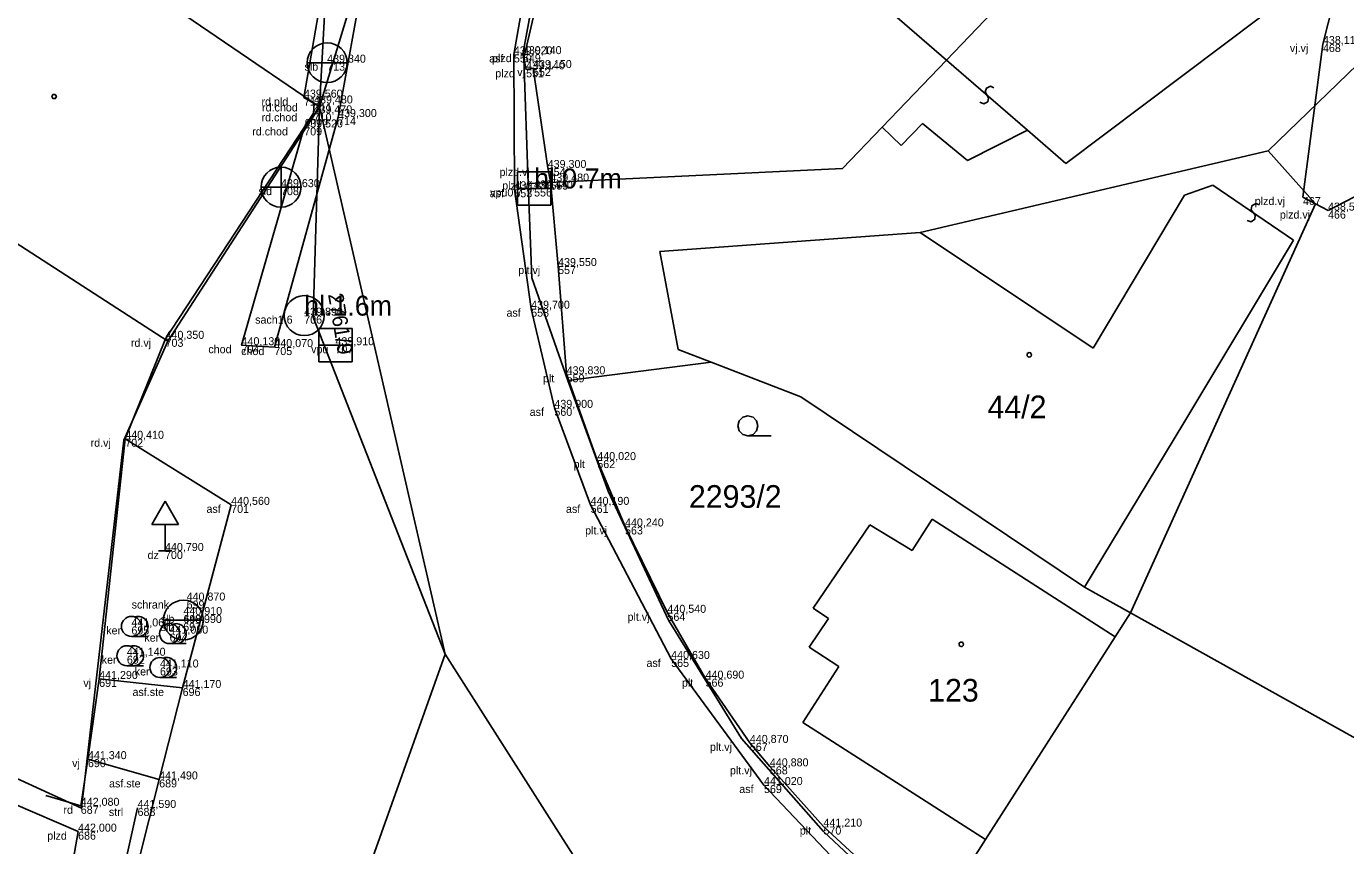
# Model space of a CAD drawing. Extents: x -747792 to -745414, y -1093712 to -1091463.
# Drawn here: x -746697.99 to -746648.52, y -1093111.16 to -1093080.43 of the extents above; entities that cross this region are included whole.
import ezdxf

# ---------------------------------------------------------------- set-up
doc = ezdxf.new("R2010")
doc.units = 0
for name, color, linetype in [('Budovy', 7, 'Continuous'), ('Hladina', 7, 'Continuous'), ('Koleje_dopravní prvky', 7, 'Continuous'), ('Kultury', 7, 'Continuous'), ('Nezařazené objekty', 7, 'Continuous'), ('Nivelační značky_hrany', 7, 'Continuous'), ('Názvy obcí_ulic', 7, 'Continuous'), ('Ploty_opěrné zdi', 7, 'Continuous'), ('Popisy objektů_povrchů', 7, 'Continuous'), ('Pracovní_bod JDTM STC_VC - výška', 7, 'Continuous'), ('Pracovní_bod PPBP - výška', 7, 'Continuous'), ('Pracovní_bod PPBP - číslo', 7, 'Continuous'), ('Pracovní_bod ZPBP - číslo', 7, 'Continuous'), ('Rozhraní ploch', 7, 'Continuous'), ('Stromy_porost', 7, 'Continuous'), ('Výškopis', 7, 'Continuous'), ('Čísla popisná_parcelní', 7, 'Continuous')]:
    doc.layers.add(name, color=color, linetype=linetype)

msp = doc.modelspace()

# ---------------------------------------------------------------- linework, layer by layer
at = {"layer": 'Budovy'}
msp.add_lwpolyline([(-746670.93, -1093095.79), (-746671.12, -1093095.74), (-746671.255, -1093095.6), (-746671.305, -1093095.415), (-746671.255, -1093095.23), (-746671.12, -1093095.09), (-746670.93, -1093095.04), (-746670.74, -1093095.09), (-746670.605, -1093095.23), (-746670.555, -1093095.415), (-746670.605, -1093095.6), (-746670.74, -1093095.74), (-746670.93, -1093095.79), (-746670.055, -1093095.79)], dxfattribs=at)
at = {"layer": 'Hladina'}
for p, q in [((-746649.37, -1093081.09), (-746649.37, -1093081.09)), ((-746686.71, -1093081.79), (-746686.71, -1093081.79)), ((-746679.71, -1093081.48), (-746679.71, -1093081.48)), ((-746679.37, -1093081.47), (-746679.37, -1093081.47)), ((-746679.25, -1093082.04), (-746679.25, -1093082.04)), ((-746678.99, -1093081.99), (-746678.99, -1093081.99)), ((-746687.58, -1093083.1), (-746687.58, -1093083.1)), ((-746687.2, -1093083.32), (-746687.2, -1093083.32)), ((-746687.22, -1093083.69), (-746687.22, -1093083.69)), ((-746686.3, -1093083.83), (-746686.3, -1093083.83)), ((-746687.57, -1093084.22), (-746687.57, -1093084.22)), ((-746678.44, -1093085.74), (-746678.44, -1093085.74)), ((-746678.34, -1093086.25), (-746678.34, -1093086.25)), ((-746688.44, -1093086.46), (-746688.44, -1093086.46)), ((-746679.69, -1093086.54), (-746679.69, -1093086.54)), ((-746678.95, -1093086.51), (-746678.95, -1093086.51)), ((-746650.12, -1093086.83), (-746650.12, -1093086.83)), ((-746649.18, -1093087.34), (-746649.18, -1093087.34)), ((-746678.05, -1093089.42), (-746678.05, -1093089.42)), ((-746687.57, -1093091.28), (-746687.57, -1093091.28)), ((-746679.06, -1093091.02), (-746679.06, -1093091.02)), ((-746692.77, -1093092.15), (-746692.77, -1093092.15)), ((-746689.92, -1093092.39), (-746689.92, -1093092.39)), ((-746688.69, -1093092.46), (-746688.69, -1093092.46)), ((-746686.4, -1093092.39), (-746686.4, -1093092.39)), ((-746677.73, -1093093.48), (-746677.73, -1093093.48)), ((-746678.19, -1093094.74), (-746678.19, -1093094.74)), ((-746694.28, -1093095.9), (-746694.28, -1093095.9)), ((-746676.58, -1093096.7), (-746676.58, -1093096.7)), ((-746690.31, -1093098.38), (-746690.31, -1093098.38)), ((-746676.83, -1093098.38), (-746676.83, -1093098.38)), ((-746675.54, -1093099.19), (-746675.54, -1093099.19)), ((-746692.79, -1093100.11), (-746692.79, -1093100.11)), ((-746691.98, -1093101.97), (-746691.98, -1093101.97)), ((-746692.1, -1093102.51), (-746692.1, -1093102.51)), ((-746673.95, -1093102.43), (-746673.95, -1093102.43)), ((-746694.05, -1093102.94), (-746694.05, -1093102.94)), ((-746692.62, -1093103.21), (-746692.62, -1093103.21)), ((-746692.11, -1093102.81), (-746692.11, -1093102.81)), ((-746694.22, -1093104.04), (-746694.22, -1093104.04)), ((-746673.81, -1093104.16), (-746673.81, -1093104.16)), ((-746692.98, -1093104.48), (-746692.98, -1093104.48)), ((-746695.26, -1093104.91), (-746695.26, -1093104.91)), ((-746672.52, -1093104.9), (-746672.52, -1093104.9)), ((-746692.13, -1093105.25), (-746692.13, -1093105.25)), ((-746670.86, -1093107.31), (-746670.86, -1093107.31)), ((-746695.68, -1093107.92), (-746695.68, -1093107.92)), ((-746670.11, -1093108.19), (-746670.11, -1093108.19)), ((-746693.01, -1093108.68), (-746693.01, -1093108.68)), ((-746670.33, -1093108.89), (-746670.33, -1093108.89)), ((-746695.95, -1093109.67), (-746695.95, -1093109.67)), ((-746693.82, -1093109.75), (-746693.82, -1093109.75)), ((-746696.05, -1093110.64), (-746696.05, -1093110.64)), ((-746668.1, -1093110.45), (-746668.1, -1093110.45))]:
    msp.add_line(p, q, dxfattribs=at)
at = {"layer": 'Kultury'}
for points in [[(-746675.52, -1093071.26), (-746663.49, -1093081.69)], [(-746697.68, -1093076.15), (-746687, -1093083.45)], [(-746660.45, -1093084.32), (-746663.49, -1093081.69)], [(-746662.234, -1093083.272), (-746662.088, -1093083.333), (-746661.941, -1093083.255), (-746661.906, -1093083.107), (-746662.032, -1093082.885), (-746661.986, -1093082.74), (-746661.838, -1093082.676), (-746661.706, -1093082.738)], [(-746704, -1093084.92), (-746692.69, -1093092.24)], [(-746654.56, -1093086.76), (-746653.5, -1093086.39)], [(-746650.47, -1093088.45), (-746653.5, -1093086.39)], [(-746657.98, -1093092.5), (-746654.56, -1093086.76)], [(-746652.216, -1093087.716), (-746652.064, -1093087.759), (-746651.928, -1093087.665), (-746651.91, -1093087.514), (-746652.06, -1093087.308), (-746652.031, -1093087.159), (-746651.892, -1093087.078), (-746651.754, -1093087.124)], [(-746664.47, -1093088.16), (-746657.98, -1093092.5)], [(-746654.59, -1093095.3), (-746650.47, -1093088.45)], [(-746658.31, -1093101.47), (-746654.59, -1093095.3)]]:
    msp.add_lwpolyline(points, dxfattribs=at)
at = {"layer": 'Nezařazené objekty'}
for points in [[(-746678.99, -1093081.99), (-746679.25, -1093082.04), (-746679.37, -1093081.47), (-746678.95, -1093079.16), (-746678.16, -1093076.39), (-746677.05, -1093073.87), (-746675.55, -1093071.24)], [(-746687.58, -1093083.1), (-746686.77, -1093078.39), (-746686.2, -1093076.08), (-746685.66, -1093074.34)], [(-746678.34, -1093086.25), (-746678.44, -1093085.74)], [(-746649.18, -1093087.34), (-746650.12, -1093086.83)], [(-746675.54, -1093099.19), (-746676.58, -1093096.7), (-746677.73, -1093093.48), (-746678.05, -1093089.42)], [(-746670.86, -1093107.31), (-746672.52, -1093104.9), (-746673.95, -1093102.43)], [(-746664.26, -1093113.75), (-746666.3, -1093112.11), (-746668.1, -1093110.45), (-746670.11, -1093108.19)], [(-746696.94, -1093115.72), (-746696.05, -1093110.64), (-746698.49, -1093109.58)]]:
    msp.add_lwpolyline(points, dxfattribs=at)
at = {"layer": 'Nivelační značky_hrany'}
for points in [[(-746660.99, -1093060), (-746658.44, -1093054.36), (-746660.29, -1093053.55), (-746661.8, -1093053.25), (-746663.42, -1093053.5), (-746664.3, -1093053.85), (-746664.96, -1093054.44), (-746666.14, -1093054.24), (-746674.99, -1093068.6), (-746677.6, -1093073.69), (-746678.64, -1093076.35), (-746679.29, -1093079.05), (-746679.71, -1093081.48), (-746679.69, -1093086.54), (-746679.06, -1093091.02), (-746678.19, -1093094.74), (-746676.83, -1093098.38), (-746673.81, -1093104.16), (-746670.33, -1093108.89), (-746666.68, -1093112.75), (-746659.26, -1093118.75), (-746651.34, -1093125.01), (-746630.74, -1093138.49)], [(-746675.68, -1093055.2), (-746675.11, -1093056), (-746675.34, -1093056.75), (-746680.83, -1093065.77), (-746683.01, -1093071), (-746684.01, -1093073.81), (-746684.88, -1093076.49), (-746685.33, -1093078.52), (-746686.3, -1093083.83), (-746688.69, -1093092.46), (-746689.92, -1093092.39), (-746687.57, -1093084.22)], [(-746696.94, -1093115.72), (-746694.86, -1093116.03), (-746693.01, -1093108.68), (-746692.13, -1093105.25), (-746690.31, -1093098.38), (-746694.28, -1093095.9)], [(-746695.26, -1093104.91), (-746692.13, -1093105.25)], [(-746695.68, -1093107.92), (-746693.01, -1093108.68)]]:
    msp.add_lwpolyline(points, dxfattribs=at)
at = {"layer": 'Názvy obcí_ulic'}
for p, q in [((-746692.79, -1093098.244), (-746693.29, -1093099.11)), ((-746692.79, -1093098.244), (-746692.29, -1093099.11)), ((-746693.29, -1093099.11), (-746692.29, -1093099.11)), ((-746692.79, -1093100.11), (-746692.79, -1093099.11)), ((-746693.04, -1093100.11), (-746692.54, -1093100.11))]:
    msp.add_line(p, q, dxfattribs=at)
at = {"layer": 'Ploty_opěrné zdi'}
for points in [[(-746696.905, -1093082.985), (-746696.86, -1093083.06), (-746696.905, -1093083.135), (-746696.995, -1093083.135), (-746697.04, -1093083.06), (-746696.995, -1093082.985)], [(-746660.38, -1093092.665), (-746660.33, -1093092.675), (-746660.305, -1093092.72), (-746660.295, -1093092.75), (-746660.305, -1093092.795), (-746660.345, -1093092.83), (-746660.38, -1093092.835), (-746660.425, -1093092.82), (-746660.455, -1093092.79), (-746660.465, -1093092.75), (-746660.455, -1093092.705), (-746660.415, -1093092.67)], [(-746662.93, -1093103.525), (-746662.88, -1093103.535), (-746662.855, -1093103.58), (-746662.845, -1093103.61), (-746662.855, -1093103.655), (-746662.895, -1093103.69), (-746662.93, -1093103.695), (-746662.975, -1093103.68), (-746663.005, -1093103.65), (-746663.015, -1093103.61), (-746663.005, -1093103.565), (-746662.965, -1093103.53)]]:
    msp.add_lwpolyline(points, close=True, dxfattribs=at)
at = {"layer": 'Popisy objektů_povrchů'}
for points in [[(-746692.77, -1093092.15), (-746687.57, -1093084.22), (-746687.22, -1093083.69), (-746687.2, -1093083.32), (-746687.58, -1093083.1)], [(-746695.26, -1093104.91), (-746694.28, -1093095.9)], [(-746695.68, -1093107.92), (-746695.26, -1093104.91)], [(-746697.26, -1093109.28), (-746695.95, -1093109.67), (-746695.68, -1093107.92)]]:
    msp.add_lwpolyline(points, dxfattribs=at)
at = {"layer": 'Pracovní_bod JDTM STC_VC - výška'}
msp.add_lwpolyline([(-746693.82, -1093109.75), (-746694.88, -1093114.52)], dxfattribs=at)
at = {"layer": 'Pracovní_bod PPBP - výška'}
for points in [[(-746650.12, -1093086.83), (-746649.37, -1093081.09), (-746648.4, -1093077.24)], [(-746678.44, -1093085.74), (-746678.99, -1093081.99)], [(-746649.18, -1093087.34), (-746645.98, -1093085.67)], [(-746678.05, -1093089.42), (-746678.34, -1093086.25)], [(-746694.28, -1093095.9), (-746692.77, -1093092.15)], [(-746673.95, -1093102.43), (-746675.54, -1093099.19)], [(-746670.11, -1093108.19), (-746670.86, -1093107.31)]]:
    msp.add_lwpolyline(points, dxfattribs=at)
at = {"layer": 'Pracovní_bod PPBP - číslo'}
for p, q in [((-746694.05, -1093103.315), (-746693.425, -1093103.315)), ((-746692.62, -1093103.585), (-746691.995, -1093103.585)), ((-746694.22, -1093104.415), (-746693.595, -1093104.415)), ((-746692.98, -1093104.855), (-746692.355, -1093104.855))]:
    msp.add_line(p, q, dxfattribs=at)
for centre in [(-746694.05, -1093102.94), (-746692.62, -1093103.21), (-746694.22, -1093104.04), (-746692.98, -1093104.48)]:
    msp.add_circle(centre, 0.375, dxfattribs=at)
for centre in [(-746693.8, -1093102.94), (-746692.37, -1093103.21), (-746693.97, -1093104.04), (-746692.73, -1093104.48)]:
    msp.add_arc(centre, 0.375, 249.4944, 109.0474, dxfattribs=at)
at = {"layer": 'Stromy_porost'}
for points in [[(-746663.49, -1093081.69), (-746656.88, -1093074.79)], [(-746679.34, -1093081.62), (-746678.21, -1093076.74)], [(-746686.7, -1093077.95), (-746687, -1093083.45)], [(-746685.44, -1093078.3), (-746687, -1093083.45)], [(-746659.01, -1093085.57), (-746651.7, -1093080.07)], [(-746651.42, -1093085.1), (-746647.33, -1093081.13)], [(-746679.34, -1093081.62), (-746679.17, -1093086.32)], [(-746665.9, -1093084.21), (-746663.49, -1093081.69)], [(-746692.69, -1093092.24), (-746687, -1093083.45)], [(-746687, -1093083.45), (-746687.24, -1093091.34)], [(-746682.29, -1093103.98), (-746687, -1093083.45)], [(-746667.39, -1093085.76), (-746665.9, -1093084.21)], [(-746665.9, -1093084.21), (-746665.18, -1093084.9)], [(-746665.18, -1093084.9), (-746664.38, -1093084.07)], [(-746662.7, -1093085.46), (-746664.38, -1093084.07)], [(-746662.7, -1093085.46), (-746660.45, -1093084.32)], [(-746660.45, -1093084.32), (-746659.01, -1093085.57)], [(-746664.47, -1093088.16), (-746651.42, -1093085.1)], [(-746651.42, -1093085.1), (-746649.65, -1093087.09)], [(-746679.17, -1093086.32), (-746667.39, -1093085.76)], [(-746679.17, -1093086.32), (-746679.04, -1093089.86)], [(-746649.65, -1093087.09), (-746656.59, -1093102.43)], [(-746674.23, -1093088.88), (-746664.47, -1093088.16)], [(-746673.55, -1093092.55), (-746674.23, -1093088.88)], [(-746679.04, -1093089.86), (-746677.68, -1093093.71)], [(-746687.24, -1093091.34), (-746682.29, -1093103.98)], [(-746694.34, -1093095.95), (-746692.69, -1093092.24)], [(-746672.31, -1093093.03), (-746673.55, -1093092.55)], [(-746677.68, -1093093.71), (-746672.31, -1093093.03)], [(-746668.95, -1093094.33), (-746672.31, -1093093.03)], [(-746677.68, -1093093.71), (-746676.17, -1093097.87)], [(-746658.31, -1093101.47), (-746668.95, -1093094.33)], [(-746694.34, -1093095.95), (-746695.92, -1093109.76)], [(-746676.17, -1093097.87), (-746673.91, -1093102.7)], [(-746668.48, -1093102.26), (-746666.36, -1093099.13)], [(-746666.36, -1093099.13), (-746664.77, -1093100.09)], [(-746664.77, -1093100.09), (-746664.02, -1093098.92)], [(-746657.16, -1093103.33), (-746664.02, -1093098.92)], [(-746658.31, -1093101.47), (-746656.59, -1093102.43)], [(-746673.91, -1093102.7), (-746671.17, -1093107.14)], [(-746668.63, -1093103.72), (-746667.91, -1093102.64)], [(-746667.91, -1093102.64), (-746668.48, -1093102.26)], [(-746657.16, -1093103.33), (-746656.59, -1093102.43)], [(-746656.59, -1093102.43), (-746643.05, -1093109.98)], [(-746668.63, -1093103.72), (-746667.52, -1093104.44)], [(-746657.16, -1093103.33), (-746662.02, -1093110.94)], [(-746685.84, -1093113.95), (-746682.29, -1093103.98)], [(-746682.29, -1093103.98), (-746676.87, -1093112.49)], [(-746668.87, -1093106.54), (-746667.52, -1093104.44)], [(-746695.92, -1093109.76), (-746705.71, -1093105.27)], [(-746662.02, -1093110.94), (-746668.87, -1093106.54)], [(-746671.17, -1093107.14), (-746668.1, -1093110.63)], [(-746668.1, -1093110.63), (-746666.35, -1093112.27)], [(-746662.02, -1093110.94), (-746664.05, -1093114.11)]]:
    msp.add_lwpolyline(points, dxfattribs=at)
at = {"layer": 'Čísla popisná_parcelní'}
for p, q in [((-746685.963, -1093081.79), (-746687.458, -1093081.79)), ((-746688.441, -1093087.208), (-746688.44, -1093085.713)), ((-746678.324, -1093085.883), (-746679.576, -1093085.883)), ((-746679.576, -1093085.883), (-746679.576, -1093087.137)), ((-746678.324, -1093087.137), (-746678.324, -1093085.883)), ((-746687.688, -1093086.466), (-746689.188, -1093086.461)), ((-746679.576, -1093086.509), (-746678.326, -1093086.509)), ((-746679.576, -1093087.137), (-746678.324, -1093087.137)), ((-746685.774, -1093091.763), (-746687.025, -1093091.763)), ((-746687.025, -1093091.763), (-746687.025, -1093093.017)), ((-746685.774, -1093093.017), (-746685.774, -1093091.763)), ((-746687.025, -1093092.39), (-746685.775, -1093092.39)), ((-746687.025, -1093093.017), (-746685.774, -1093093.017)), ((-746691.353, -1093102.7), (-746692.848, -1093102.7))]:
    msp.add_line(p, q, dxfattribs=at)
for centre in [(-746688.44, -1093086.46), (-746687.57, -1093091.28)]:
    msp.add_circle(centre, 0.75, dxfattribs=at)
for centre, start, end in [((-746686.71, -1093081.79), 0, 180), ((-746686.71, -1093081.79), 180, 0), ((-746692.1, -1093102.7), 0, 180), ((-746692.1, -1093102.7), 180, 0)]:
    msp.add_arc(centre, 0.747, start, end, dxfattribs=at)

# ---------------------------------------------------------------- texts
at = {"layer": 'Koleje_dopravní prvky'}
msp.add_text('2761/9', height=0.57, rotation=279.4888, dxfattribs=at).set_placement((-746686.68, -1093090.481))
for s, p in [('44/2', (-746661.949, -1093095.13)), ('2293/2', (-746673.145, -1093098.49)), ('123', (-746664.173, -1093105.76))]:
    msp.add_text(s, height=0.85, dxfattribs=at).set_placement(p)
at = {"layer": 'Pracovní_bod ZPBP - číslo'}
for s, p in [('hl.0.7m', (-746678.95, -1093086.51)), ('hl.1.6m', (-746687.57, -1093091.28))]:
    msp.add_text(s, height=0.75, dxfattribs=at).set_placement(p)
at = {"layer": 'Rozhraní ploch'}
for s, p in [(' asf', (-746680.747, -1093081.78)), (' plzd', (-746680.638, -1093081.77)), (' vj.vj', (-746650.723, -1093081.39)), ('468', (-746649.37, -1093081.39)), (' slb', (-746687.671, -1093082.09)), ('713', (-746686.71, -1093082.09)), ('550', (-746679.71, -1093081.78)), ('549', (-746679.37, -1093081.77)), (' plzd', (-746680.518, -1093082.34)), (' vj', (-746679.694, -1093082.29)), ('551', (-746679.25, -1093082.34)), ('552', (-746678.99, -1093082.29)), (' rd.pld', (-746689.285, -1093083.4)), (' rd.chod', (-746689.262, -1093083.62)), ('712', (-746687.58, -1093083.4)), ('711', (-746687.2, -1093083.62)), (' rd.chod', (-746689.282, -1093083.99)), (' chod', (-746687.656, -1093084.13)), ('710', (-746687.22, -1093083.99)), ('714', (-746686.3, -1093084.13)), (' rd.chod', (-746689.632, -1093084.52)), ('709', (-746687.57, -1093084.52)), (' plzd.vj', (-746680.358, -1093086.04)), ('554', (-746678.44, -1093086.04)), (' plzd.vj', (-746680.258, -1093086.55)), ('555', (-746678.34, -1093086.55)), (' sld', (-746689.401, -1093086.76)), ('708', (-746688.44, -1093086.76)), (' asf', (-746680.727, -1093086.84)), (' vpu0.7', (-746680.71, -1093086.81)), ('553', (-746679.69, -1093086.84)), ('556', (-746678.95, -1093086.81)), (' plzd.vj', (-746652.038, -1093087.13)), ('467', (-746650.12, -1093087.13)), (' plzd.vj', (-746651.098, -1093087.64)), ('466', (-746649.18, -1093087.64)), (' plt.vj', (-746679.658, -1093089.72)), ('557', (-746678.05, -1093089.72)), (' sach1.6', (-746689.523, -1093091.58)), ('706', (-746687.57, -1093091.58)), (' asf', (-746680.097, -1093091.32)), ('558', (-746679.06, -1093091.32)), (' rd.vj', (-746694.18, -1093092.45)), ('703', (-746692.77, -1093092.45)), (' chod', (-746691.276, -1093092.69)), (' chod', (-746690.046, -1093092.76)), ('704', (-746689.92, -1093092.69)), ('705', (-746688.69, -1093092.76)), (' vpu', (-746687.423, -1093092.69)), ('707', (-746686.4, -1093092.69)), (' plt', (-746678.729, -1093093.78)), ('559', (-746677.73, -1093093.78)), (' asf', (-746679.227, -1093095.04)), ('560', (-746678.19, -1093095.04)), (' rd.vj', (-746695.69, -1093096.2)), ('702', (-746694.28, -1093096.2)), (' plt', (-746677.579, -1093097)), ('562', (-746676.58, -1093097)), (' asf', (-746691.347, -1093098.68)), ('701', (-746690.31, -1093098.68)), (' asf', (-746677.867, -1093098.68)), ('561', (-746676.83, -1093098.68)), (' plt.vj', (-746677.148, -1093099.49)), ('563', (-746675.54, -1093099.49)), (' dz', (-746693.555, -1093100.41)), ('700', (-746692.79, -1093100.41)), (' schrank', (-746694.153, -1093102.27)), ('699', (-746691.98, -1093102.27)), (' slb', (-746693.061, -1093102.81)), ('698', (-746692.1, -1093102.81)), (' plt.vj', (-746675.558, -1093102.73)), ('564', (-746673.95, -1093102.73)), (' ker', (-746695.106, -1093103.24)), ('695', (-746694.05, -1093103.24)), (' ker', (-746693.676, -1093103.51)), (' slb', (-746693.071, -1093103.11)), ('694', (-746692.62, -1093103.51)), ('697', (-746692.11, -1093103.11)), (' ker', (-746695.276, -1093104.34)), ('692', (-746694.22, -1093104.34)), (' asf', (-746674.847, -1093104.46)), ('565', (-746673.81, -1093104.46)), (' ker', (-746694.036, -1093104.78)), ('693', (-746692.98, -1093104.78)), (' vj', (-746695.964, -1093105.21)), ('691', (-746695.26, -1093105.21)), (' plt', (-746673.519, -1093105.2)), ('566', (-746672.52, -1093105.2)), (' asf.ste', (-746694.121, -1093105.55)), ('696', (-746692.13, -1093105.55)), (' plt.vj', (-746672.468, -1093107.61)), ('567', (-746670.86, -1093107.61)), (' vj', (-746696.384, -1093108.22)), ('690', (-746695.68, -1093108.22)), (' plt.vj', (-746671.718, -1093108.49)), (' asf.ste', (-746695.001, -1093108.98)), ('568', (-746670.11, -1093108.49)), ('689', (-746693.01, -1093108.98)), (' asf', (-746671.367, -1093109.19)), ('569', (-746670.33, -1093109.19)), (' rd', (-746696.711, -1093109.97)), ('687', (-746695.95, -1093109.97)), (' strl', (-746695.006, -1093110.05)), ('688', (-746693.82, -1093110.05)), (' plzd', (-746697.318, -1093110.94)), ('686', (-746696.05, -1093110.94)), (' plt', (-746669.099, -1093110.75)), ('570', (-746668.1, -1093110.75))]:
    msp.add_text(s, height=0.3, dxfattribs=at).set_placement(p)
at = {"layer": 'Výškopis'}
for s, p in [('438,110', (-746649.37, -1093081.09)), ('439,020', (-746679.71, -1093081.48)), ('439,140', (-746679.37, -1093081.47)), ('439,340', (-746686.71, -1093081.79)), ('439,140', (-746679.25, -1093082.04)), ('439,150', (-746678.99, -1093081.99)), ('439,560', (-746687.58, -1093083.1)), ('439,470', (-746687.22, -1093083.69)), ('439,480', (-746687.2, -1093083.32)), ('439,520', (-746687.57, -1093084.22)), ('439,300', (-746686.3, -1093083.83)), ('439,300', (-746678.44, -1093085.74)), ('439,630', (-746688.44, -1093086.46)), ('439,390', (-746679.69, -1093086.54)), ('439,440', (-746678.95, -1093086.51)), ('439,480', (-746678.34, -1093086.25)), ('438,560', (-746649.18, -1093087.34)), ('439,550', (-746678.05, -1093089.42)), ('439,700', (-746679.06, -1093091.02)), ('439,890', (-746687.57, -1093091.28)), ('440,350', (-746692.77, -1093092.15)), ('440,130', (-746689.92, -1093092.39)), ('440,070', (-746688.69, -1093092.46)), ('439,910', (-746686.4, -1093092.39)), ('439,830', (-746677.73, -1093093.48)), ('439,900', (-746678.19, -1093094.74)), ('440,410', (-746694.28, -1093095.9)), ('440,020', (-746676.58, -1093096.7)), ('440,560', (-746690.31, -1093098.38)), ('440,190', (-746676.83, -1093098.38)), ('440,240', (-746675.54, -1093099.19)), ('440,790', (-746692.79, -1093100.11)), ('440,870', (-746691.98, -1093101.97)), ('440,910', (-746692.1, -1093102.51)), ('440,540', (-746673.95, -1093102.43)), ('441,060', (-746694.05, -1093102.94)), ('440,990', (-746692.11, -1093102.81)), ('441,050', (-746692.62, -1093103.21)), ('441,140', (-746694.22, -1093104.04)), ('441,110', (-746692.98, -1093104.48)), ('440,630', (-746673.81, -1093104.16)), ('441,290', (-746695.26, -1093104.91)), ('440,690', (-746672.52, -1093104.9)), ('441,170', (-746692.13, -1093105.25)), ('440,870', (-746670.86, -1093107.31)), ('441,340', (-746695.68, -1093107.92)), ('440,880', (-746670.11, -1093108.19)), ('441,490', (-746693.01, -1093108.68)), ('441,020', (-746670.33, -1093108.89)), ('442,080', (-746695.95, -1093109.67)), ('441,590', (-746693.82, -1093109.75)), ('441,210', (-746668.1, -1093110.45)), ('442,000', (-746696.05, -1093110.64))]:
    msp.add_text(s, height=0.3, dxfattribs=at).set_placement(p)

doc.saveas('drawing.dxf')
